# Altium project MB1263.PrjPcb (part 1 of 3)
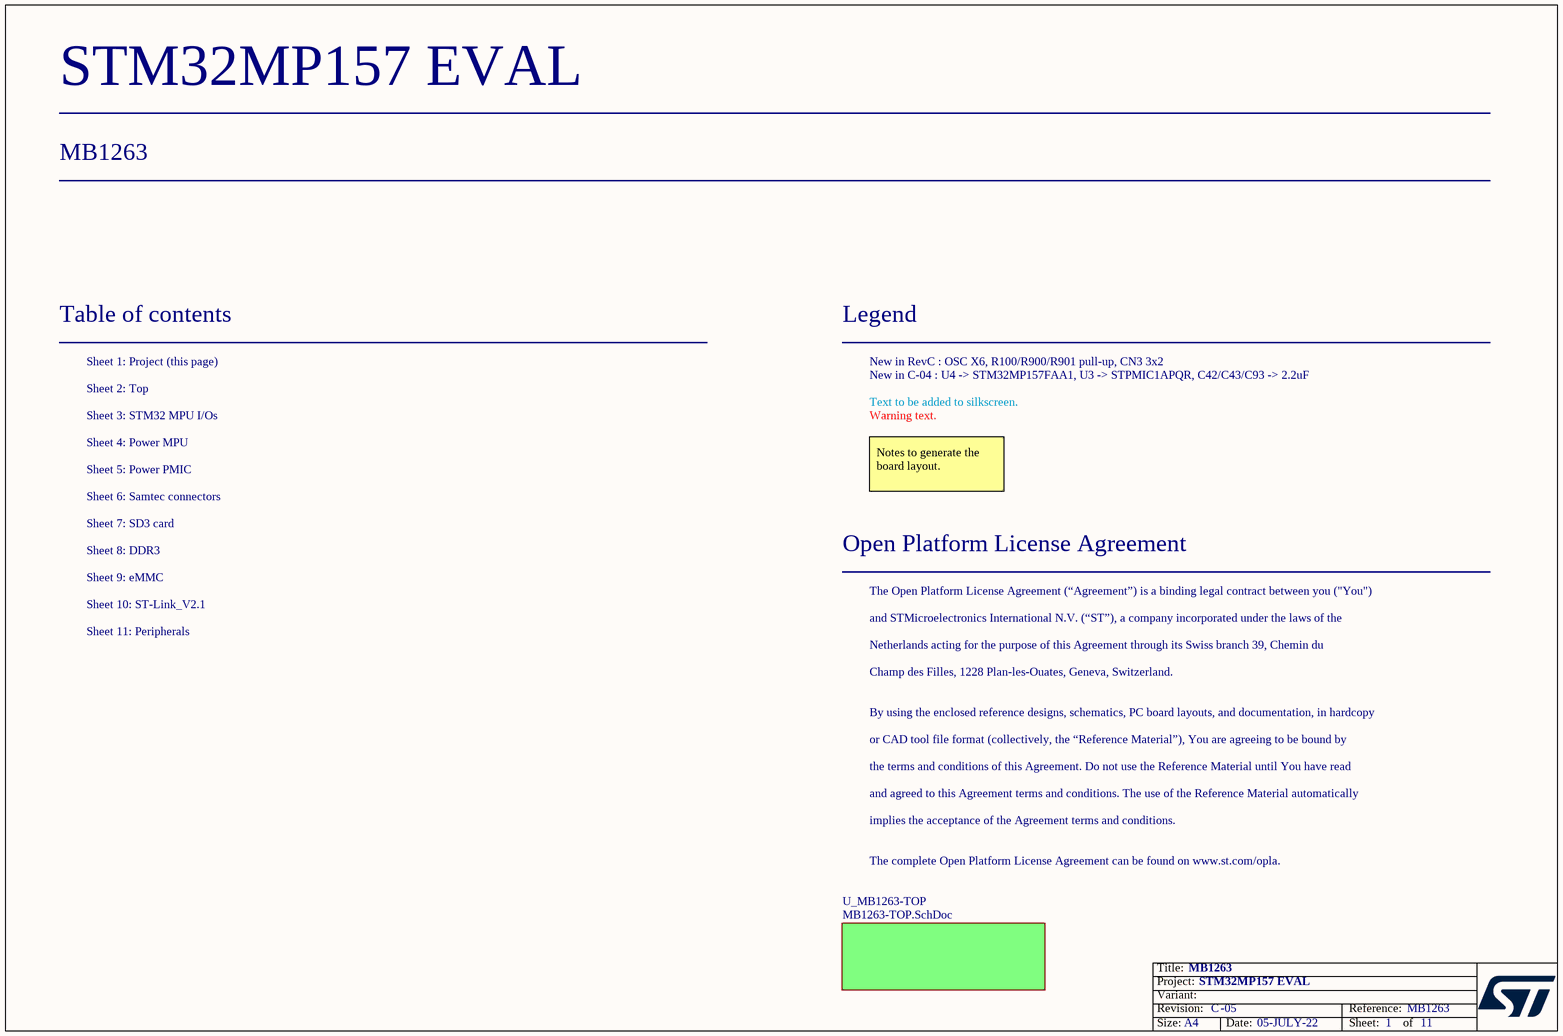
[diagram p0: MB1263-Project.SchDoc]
Board_Reference: MB1263; Board_PCB_Revision: C; Board_Name: STM32MP157 EVAL; Board_Document_Date: 05-JULY-22; Board_Assembly_Revision: 05
11 sheets, 393 parts. Net scope: flat (ports and power ports of the same name join across sheets).
Board file: MB1263.PcbDoc
Sheets:
  MB1263-Project.SchDoc
    U_MB1263-TOP = MB1263-TOP.SchDoc
      U_eMMC = eMMC.SchDoc
      U_DDR3_2x16bits = DDR3_2x16bits.SchDoc
      U_Power_PMIC = Power_PMIC.SchDoc
      U_MPU_18x18 = MPU_18x18.SchDoc
      U_SD3 card = SD3 card.SchDoc
      U_Peripherals = Peripherals.SchDoc
      U_ST_LINK_V2-1 = ST_LINK_V2-1.SCHDOC
      U_Samtec Connectors QTH_North_South = Samtec Connectors QTH_North_South.SchDoc
      U_Power_MPU = Power_MPU.SchDoc

## Sheet MB1263-Project.SchDoc: MB1263
size A4; Date: Not used; ApprovedBy: Not used; CheckedBy: Not used; Author: Not used; CompanyName: STMicroelectronics; DrawnBy: Not used; Engineer: Not used; Organization: Not used; Address1: Not used; Address2: Not used; Address3: Not used; Address4: Not used; DocumentNumber: Not used; Revision: Not used; SheetNumber: 1; SheetTotal: 11

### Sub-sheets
U_MB1263-TOP = MB1263-TOP.SchDoc: no entries

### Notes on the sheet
- Table of contents
- Sheet 1: Project (this page)
- Legend
- New in RevC : OSC X6, R100/R900/R901 pull-up, CN3 3x2
- New in C-04 : U4 -> STM32MP157FAA1, U3 -> STPMIC1APQR, C42/C43/C93 -> 2.2uF
- Sheet 2: Top
- Sheet 3: STM32 MPU I/Os
- Sheet 4: Power MPU
- Text to be added to silkscreen.
- Warning text.
- Sheet 6: Samtec connectors
- Sheet 5: Power PMIC
- Notes to generate the board layout.
- Sheet 7: SD3 card
- Sheet 9: eMMC
- Sheet 8: DDR3
- Open Platform License Agreement
- Sheet 10: ST-Link_V2.1
- Sheet 11: Peripherals
- The Open Platform License Agreement (“Agreement”) is a binding legal contract between you ("You")
- and STMicroelectronics International N.V. (“ST”), a company incorporated under the laws of the
- Netherlands acting for the purpose of this Agreement through its Swiss branch 39, Chemin du
- Champ des Filles, 1228 Plan-les-Ouates, Geneva, Switzerland.
- By using the enclosed reference designs, schematics, PC board layouts, and documentation, in hardcopy
- or CAD tool file format (collectively, the “Reference Material”), You are agreeing to be bound by
- the terms and conditions of this Agreement. Do not use the Reference Material until You have read
- and agreed to this Agreement terms and conditions. The use of the Reference Material automatically
- implies the acceptance of the Agreement terms and conditions.
- The complete Open Platform License Agreement can be found on www.st.com/opla.

## Sheet MB1263-TOP.SchDoc: MB1263-TOP
size A3; CompanyName: STMicroelectronics; DocumentNumber: MB1263; Revision: C-04; SheetNumber: 2; SheetTotal: 11; Project: STM32MP157-EVAL
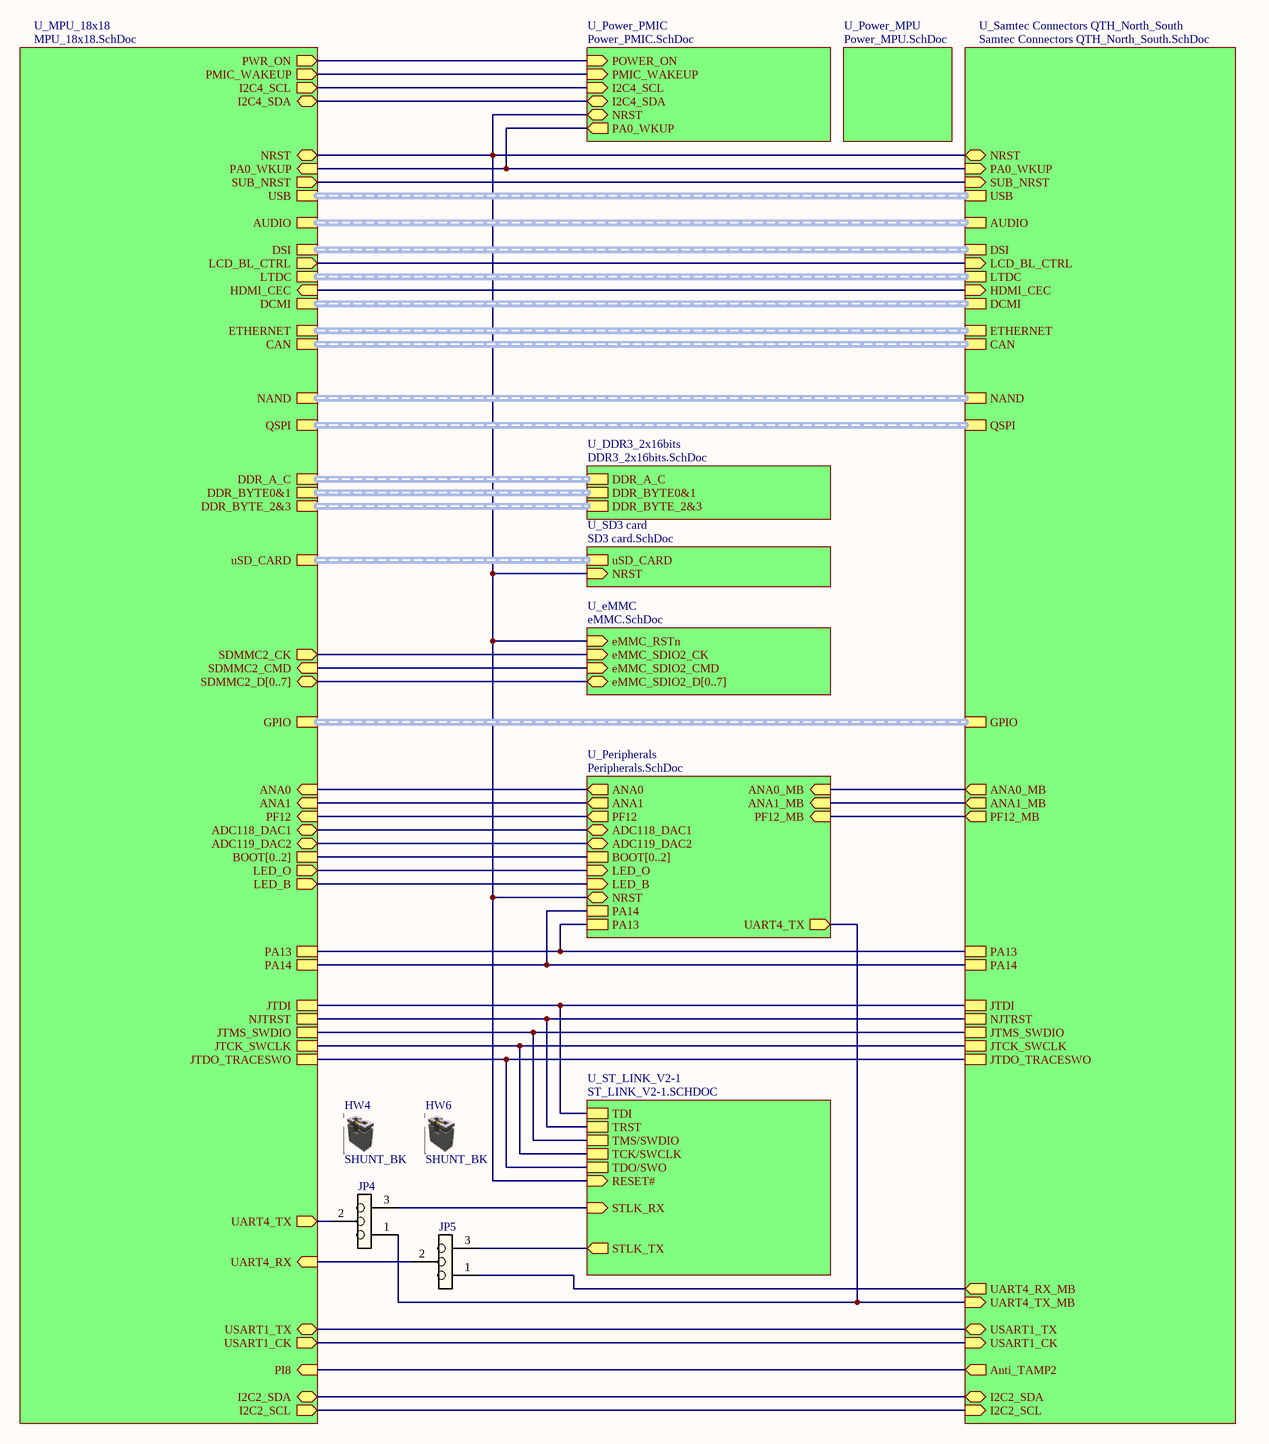
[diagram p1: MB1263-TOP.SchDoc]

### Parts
HW4  SHUNT_BK  (mechanical)
HW6  SHUNT_BK  (mechanical)
JP4  Header 3 pins  [CON_SAMTEC_TSW-103-07-F-S]  (value not drawn)
JP5  Header 3 pins  [CON_SAMTEC_TSW-103-07-F-S]  (value not drawn)

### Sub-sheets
U_DDR3_2x16bits = DDR3_2x16bits.SchDoc: DDR_A_C (harness DDR_A_C), DDR_BYTE0&1 (harness DDR_BYTE_0&1), DDR_BYTE_2&3 (harness DDR_BYTE_2&3)
U_eMMC = eMMC.SchDoc: eMMC_SDIO2_CK (in), eMMC_SDIO2_D[0..7] (bidir), eMMC_RSTn (in), eMMC_SDIO2_CMD (in)
U_MPU_18x18 = MPU_18x18.SchDoc: DDR_BYTE0&1 (harness DDR_BYTE_0&1), DDR_BYTE_2&3 (harness DDR_BYTE_2&3), DDR_A_C (harness DDR_A_C), ANA0 (in), ADC118_DAC1 (bidir), PWR_ON (out), SDMMC2_CK (out), SDMMC2_D[0..7] (bidir), SDMMC2_CMD (in), DSI (harness DSI), LCD_BL_CTRL (out), HDMI_CEC (in), USART1_TX (bidir), USART1_CK (out), CAN (harness CAN), JTMS_SWDIO, JTDI, JTDO_TRACESWO, NJTRST, JTCK_SWCLK, PA13, PA14, I2C4_SDA (bidir), I2C4_SCL (out), PA0_WKUP (in), PMIC_WAKEUP (out), NRST (bidir), UART4_TX (out), UART4_RX (in), ADC119_DAC2 (bidir), ANA1 (in), GPIO (harness GPIO), PI8 (in), USB (harness USB), NAND (harness NAND), LTDC (harness LTDC), DCMI (harness DCMI), ETHERNET (harness ETHERNET), QSPI (harness QSPI), AUDIO (harness AUDIO), uSD_CARD (harness uSD_CARD), PF12 (in), BOOT[0..2], I2C2_SDA (bidir), I2C2_SCL (out), LED_O (out), LED_B (out), SUB_NRST (out)
U_Peripherals = Peripherals.SchDoc: ADC118_DAC1 (bidir), ADC119_DAC2 (bidir), NRST (bidir), ANA0 (out), ANA1 (out), BOOT[0..2], PA13, PA14, UART4_TX (out), ANA0_MB (in), ANA1_MB (in), PF12 (out), PF12_MB (in), LED_O (in), LED_B (in)
U_Power_MPU = Power_MPU.SchDoc: no entries
U_Power_PMIC = Power_PMIC.SchDoc: I2C4_SDA (bidir), I2C4_SCL (in), PA0_WKUP (out), NRST (bidir), POWER_ON (in), PMIC_WAKEUP (in)
U_Samtec Connectors QTH_North_South = Samtec Connectors QTH_North_South.SchDoc: Anti_TAMP2 (out), USART1_TX (bidir), USART1_CK (in), GPIO (harness GPIO), LCD_BL_CTRL (in), DSI (harness DSI), JTMS_SWDIO, JTCK_SWCLK, JTDI, NJTRST, JTDO_TRACESWO, NRST (bidir), PA0_WKUP (in), CAN (harness CAN), UART4_TX_MB (in), UART4_RX_MB (out), PA13, PA14, HDMI_CEC (in), USB (harness USB), NAND (harness NAND), LTDC (harness LTDC), DCMI (harness DCMI), ETHERNET (harness ETHERNET), QSPI (harness QSPI), AUDIO (harness AUDIO), PF12_MB (out), ANA0_MB (out), ANA1_MB (out), I2C2_SCL (in), I2C2_SDA (bidir), SUB_NRST (in)
U_SD3 card = SD3 card.SchDoc: uSD_CARD (harness uSD_CARD), NRST (in)
U_ST_LINK_V2-1 = ST_LINK_V2-1.SCHDOC: STLK_RX (in), STLK_TX (out), TDI, TRST, TMS/SWDIO, TCK/SWCLK, TDO/SWO, RESET# (in)

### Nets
NetJP4_1: JP4.1 ; sheet U_Peripherals/UART4_TX, sheet U_Samtec Connectors QTH_North_South/UART4_TX_MB
NetJP4_2: JP4.2 ; sheet U_MPU_18x18/UART4_TX
NetJP4_3: JP4.3 ; sheet U_ST_LINK_V2-1/STLK_RX
NetJP5_1: JP5.1 ; sheet U_Samtec Connectors QTH_North_South/UART4_RX_MB
NetJP5_2: JP5.2 ; sheet U_MPU_18x18/UART4_RX
NetJP5_3: JP5.3 ; sheet U_ST_LINK_V2-1/STLK_TX
(unnamed): sheet U_eMMC/eMMC_SDIO2_CK, sheet U_MPU_18x18/SDMMC2_CK
(unnamed): sheet U_eMMC/eMMC_RSTn, sheet U_Power_PMIC/NRST, sheet U_MPU_18x18/NRST, sheet U_SD3 card/NRST, sheet U_Peripherals/NRST, sheet U_ST_LINK_V2-1/RESET#, sheet U_Samtec Connectors QTH_North_South/NRST  [a separate net that carries the same name]
(unnamed): sheet U_eMMC/eMMC_SDIO2_CMD, sheet U_MPU_18x18/SDMMC2_CMD  [a separate net that carries the same name]
(unnamed): sheet U_Power_PMIC/I2C4_SDA, sheet U_MPU_18x18/I2C4_SDA  [a separate net that carries the same name]
(unnamed): sheet U_Power_PMIC/I2C4_SCL, sheet U_MPU_18x18/I2C4_SCL  [a separate net that carries the same name]
(unnamed): sheet U_Power_PMIC/PA0_WKUP, sheet U_MPU_18x18/PA0_WKUP, sheet U_Samtec Connectors QTH_North_South/PA0_WKUP  [a separate net that carries the same name]
(unnamed): sheet U_Power_PMIC/POWER_ON, sheet U_MPU_18x18/PWR_ON  [a separate net that carries the same name]
(unnamed): sheet U_Power_PMIC/PMIC_WAKEUP, sheet U_MPU_18x18/PMIC_WAKEUP  [a separate net that carries the same name]
(unnamed): sheet U_MPU_18x18/ANA0, sheet U_Peripherals/ANA0  [a separate net that carries the same name]
(unnamed): sheet U_MPU_18x18/ADC118_DAC1, sheet U_Peripherals/ADC118_DAC1  [a separate net that carries the same name]
(unnamed): sheet U_MPU_18x18/LCD_BL_CTRL, sheet U_Samtec Connectors QTH_North_South/LCD_BL_CTRL  [a separate net that carries the same name]
(unnamed): sheet U_MPU_18x18/HDMI_CEC, sheet U_Samtec Connectors QTH_North_South/HDMI_CEC  [a separate net that carries the same name]
(unnamed): sheet U_MPU_18x18/USART1_TX, sheet U_Samtec Connectors QTH_North_South/USART1_TX  [a separate net that carries the same name]
(unnamed): sheet U_MPU_18x18/USART1_CK, sheet U_Samtec Connectors QTH_North_South/USART1_CK  [a separate net that carries the same name]
(unnamed): sheet U_MPU_18x18/JTMS_SWDIO, sheet U_ST_LINK_V2-1/TMS/SWDIO, sheet U_Samtec Connectors QTH_North_South/JTMS_SWDIO  [a separate net that carries the same name]
(unnamed): sheet U_MPU_18x18/JTDI, sheet U_ST_LINK_V2-1/TDI, sheet U_Samtec Connectors QTH_North_South/JTDI  [a separate net that carries the same name]
(unnamed): sheet U_MPU_18x18/JTDO_TRACESWO, sheet U_ST_LINK_V2-1/TDO/SWO, sheet U_Samtec Connectors QTH_North_South/JTDO_TRACESWO  [a separate net that carries the same name]
(unnamed): sheet U_MPU_18x18/NJTRST, sheet U_ST_LINK_V2-1/TRST, sheet U_Samtec Connectors QTH_North_South/NJTRST  [a separate net that carries the same name]
(unnamed): sheet U_MPU_18x18/JTCK_SWCLK, sheet U_ST_LINK_V2-1/TCK/SWCLK, sheet U_Samtec Connectors QTH_North_South/JTCK_SWCLK  [a separate net that carries the same name]
(unnamed): sheet U_MPU_18x18/PA13, sheet U_Peripherals/PA13, sheet U_Samtec Connectors QTH_North_South/PA13  [a separate net that carries the same name]
(unnamed): sheet U_MPU_18x18/PA14, sheet U_Peripherals/PA14, sheet U_Samtec Connectors QTH_North_South/PA14  [a separate net that carries the same name]
(unnamed): sheet U_MPU_18x18/ADC119_DAC2, sheet U_Peripherals/ADC119_DAC2  [a separate net that carries the same name]
(unnamed): sheet U_MPU_18x18/ANA1, sheet U_Peripherals/ANA1  [a separate net that carries the same name]
(unnamed): sheet U_MPU_18x18/PI8, sheet U_Samtec Connectors QTH_North_South/Anti_TAMP2  [a separate net that carries the same name]
(unnamed): sheet U_MPU_18x18/PF12, sheet U_Peripherals/PF12  [a separate net that carries the same name]
(unnamed): sheet U_MPU_18x18/I2C2_SDA, sheet U_Samtec Connectors QTH_North_South/I2C2_SDA  [a separate net that carries the same name]
(unnamed): sheet U_MPU_18x18/I2C2_SCL, sheet U_Samtec Connectors QTH_North_South/I2C2_SCL  [a separate net that carries the same name]
(unnamed): sheet U_MPU_18x18/LED_O, sheet U_Peripherals/LED_O  [a separate net that carries the same name]
(unnamed): sheet U_MPU_18x18/LED_B, sheet U_Peripherals/LED_B  [a separate net that carries the same name]
(unnamed): sheet U_MPU_18x18/SUB_NRST, sheet U_Samtec Connectors QTH_North_South/SUB_NRST  [a separate net that carries the same name]
(unnamed): sheet U_Peripherals/ANA0_MB, sheet U_Samtec Connectors QTH_North_South/ANA0_MB  [a separate net that carries the same name]
(unnamed): sheet U_Peripherals/ANA1_MB, sheet U_Samtec Connectors QTH_North_South/ANA1_MB  [a separate net that carries the same name]
(unnamed): sheet U_Peripherals/PF12_MB, sheet U_Samtec Connectors QTH_North_South/PF12_MB  [a separate net that carries the same name]

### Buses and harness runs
bus sheet U_eMMC/eMMC_SDIO2_D[0..7] = sheet U_MPU_18x18/SDMMC2_D[0..7]
bus sheet U_MPU_18x18/BOOT[0..2] = sheet U_Peripherals/BOOT[0..2]
harness sheet U_DDR3_2x16bits/DDR_A_C = sheet U_MPU_18x18/DDR_A_C
harness sheet U_DDR3_2x16bits/DDR_BYTE0&1 = sheet U_MPU_18x18/DDR_BYTE0&1
harness sheet U_DDR3_2x16bits/DDR_BYTE_2&3 = sheet U_MPU_18x18/DDR_BYTE_2&3
harness sheet U_MPU_18x18/AUDIO = sheet U_Samtec Connectors QTH_North_South/AUDIO
harness sheet U_MPU_18x18/CAN = sheet U_Samtec Connectors QTH_North_South/CAN
harness sheet U_MPU_18x18/DCMI = sheet U_Samtec Connectors QTH_North_South/DCMI
harness sheet U_MPU_18x18/DSI = sheet U_Samtec Connectors QTH_North_South/DSI
harness sheet U_MPU_18x18/ETHERNET = sheet U_Samtec Connectors QTH_North_South/ETHERNET
harness sheet U_MPU_18x18/GPIO = sheet U_Samtec Connectors QTH_North_South/GPIO
harness sheet U_MPU_18x18/LTDC = sheet U_Samtec Connectors QTH_North_South/LTDC
harness sheet U_MPU_18x18/NAND = sheet U_Samtec Connectors QTH_North_South/NAND
harness sheet U_MPU_18x18/QSPI = sheet U_Samtec Connectors QTH_North_South/QSPI
harness sheet U_MPU_18x18/USB = sheet U_Samtec Connectors QTH_North_South/USB
harness sheet U_MPU_18x18/uSD_CARD = sheet U_SD3 card/uSD_CARD

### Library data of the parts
HW4 HW6 = Shunt 2.54mm: SHUNT 2.54mm BLACK; Manuf_1: SAMTEC; Manuf_Part_1: SNT-100-BK-G; Fitted: YES; Ordered_By: Subcon
JP4 JP5 = Header 3: Header, 3-Pin; Manuf_1: Samtec; Manuf_Part_1: TSW-103-07-F-S; Fitted: YES; Ordered_By: Subcon

## Sheet eMMC.SchDoc: eMMC
size A4; CompanyName: STMicroelectronics; DocumentNumber: MB1263; Revision: C-04; SheetNumber: 9; SheetTotal: 11; Project: STM32MP157-EVAL
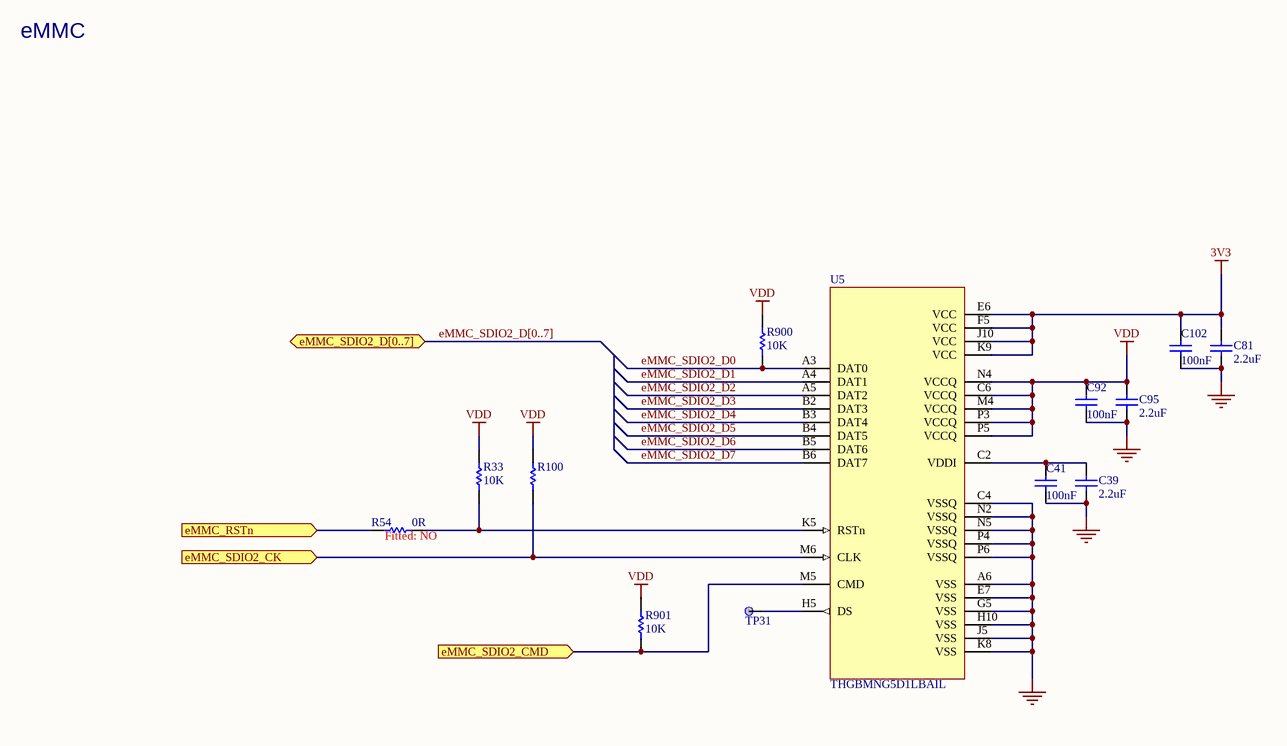
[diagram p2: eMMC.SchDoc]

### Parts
C39  2.2uF  [C0603]
C41  100nF  [C0402]
C81  2.2uF  [C0603]
C92  100nF  [C0402]
C95  2.2uF  [C0603]
C102  100nF  [C0402]
R33  10K  [R0402]
R54  0R  Fitted: NO  [R0402]
R100  10K  [R0402]  (value not drawn)
R900  10K  [R0402]
R901  10K  [R0402]
TP31  TP  [TP_SMD_1MM]  (value not drawn)  (no BOM)
U5  THGBMNG5D1LBAIL  [ICC_P-WFBGA153_13X11P5_P050]

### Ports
eMMC_RSTn (in), eMMC_SDIO2_CK (in), eMMC_SDIO2_CMD (in), eMMC_SDIO2_D[0..7] (bidir)

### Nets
3V3: C81.1 C102.2 U5.E6(VCC) U5.F5(VCC) U5.J10(VCC) U5.K9(VCC)
GND: C39.2 C41.1 C81.2 C92.1 C95.2 C102.1 U5.A6(VSS) U5.C4(VSSQ) U5.E7(VSS) U5.G5(VSS) U5.H10(VSS) U5.J5(VSS) U5.K8(VSS) U5.N2(VSSQ) U5.N5(VSSQ) U5.P4(VSSQ) U5.P6(VSSQ)
VDD: C92.2 C95.1 R33.2 R100.2 R900.2 R901.2 U5.C6(VCCQ) U5.M4(VCCQ) U5.N4(VCCQ) U5.P3(VCCQ) U5.P5(VCCQ)
eMMC_RSTn: R54.1 ; port eMMC_RSTn
eMMC_SDIO2_CK: R100.1 U5.M6(CLK) ; port eMMC_SDIO2_CK
eMMC_SDIO2_CMD: R901.1 U5.M5(CMD) ; port eMMC_SDIO2_CMD
eMMC_SDIO2_D0: R900.1 U5.A3(DAT0)
eMMC_SDIO2_D1: U5.A4(DAT1)
eMMC_SDIO2_D2: U5.A5(DAT2)
eMMC_SDIO2_D3: U5.B2(DAT3)
eMMC_SDIO2_D4: U5.B3(DAT4)
eMMC_SDIO2_D5: U5.B4(DAT5)
eMMC_SDIO2_D6: U5.B5(DAT6)
eMMC_SDIO2_D7: U5.B6(DAT7)
NetC39_1: C39.1 C41.2 U5.C2(VDDI)
NetR33_1: R33.1 R54.2 U5.K5(RSTn)
NetTP31_1: TP31.1 U5.H5(DS)

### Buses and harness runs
bus eMMC_SDIO2_D[0..7] = port eMMC_SDIO2_D[0..7]

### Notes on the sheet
- eMMC

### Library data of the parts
C39 C81 C95 = Cap_2.2uF_X5R_10%_0603: Capacitor,2.2uF,10V, X5R,10%,0603,YAGEO; Manuf_Part_1: CC0603KRX5R6BB225; Manuf_Part_2: C0603C225K8PACTU; Manuf_2: KEMET; Fitted: YES; Ordered_By: Subcon
C41 C92 C102 = Cap_100nF_X7R_10%_0402: Capacitor,100nF,16V,X7R,10%,0402,YAGEO; Manuf_Part_1: CC0402KRX7R7BB104; Fitted: YES; Ordered_By: Subcon
R33 R100 R900 R901 = Res_10K_1%_0402: Resistor,10K,0402,1%,YAGEO; Manuf_Part_1: RC0402FR-0710KL; Order_Code: 9239359RL; Fitted: YES; Ordered_By: Subcon
R54 = Res_0_5%_0402: Resistor,0R,0402,5%,YAGEO; Manuf_Part_1: RC0402JR-070RL; Order_Code: 2363467; Ordered_By: Subcon
TP31 = TP 1mm: Test Point; Fitted: YES
U5 = eMMC_THGBMNG5D1LBAIL: eMMC 4GB 153 Balls WFBGA 15nm; Manuf_1: KIOXIA; Manuf_Part_1: THGBMTG5D1LBAIL; ECCN_US/EU: EAR99; Fitted: YES; Ordered_By: Subcon

## Sheet DDR3_2x16bits.SchDoc: 2X DDR3L 16 bits
size A4; Date: 30-MAR-2016; Author: F.L; CompanyName: STMicroelectronics; Organization: MCD/TOOLS/LMS; Address1: 12, Rue Jules HOROWITZ; Address2: 38019 Grenoble; Address3: FRANCE; DocumentNumber: MB1263; Revision: C-04; SheetNumber: 8; SheetTotal: 11; Project: STM32MP157-EVAL; PageSetup: Record=PageOptions¦CenterHorizontal=True¦CenterVertical=True¦PrintScale=1.39¦XCorrection=1.00¦YCorrection=1.00¦PrintKind=1¦BorderSize=5000000¦LeftOffset=0¦BottomOffset=0¦Orientation=2¦PaperLength=1000¦PaperWidth=1000¦Scale=100¦PaperSource=15¦PrintQuality=600¦MediaType=1¦DitherType=10¦PrintScaleMode=1¦PaperKind=A3¦PaperIndex=8
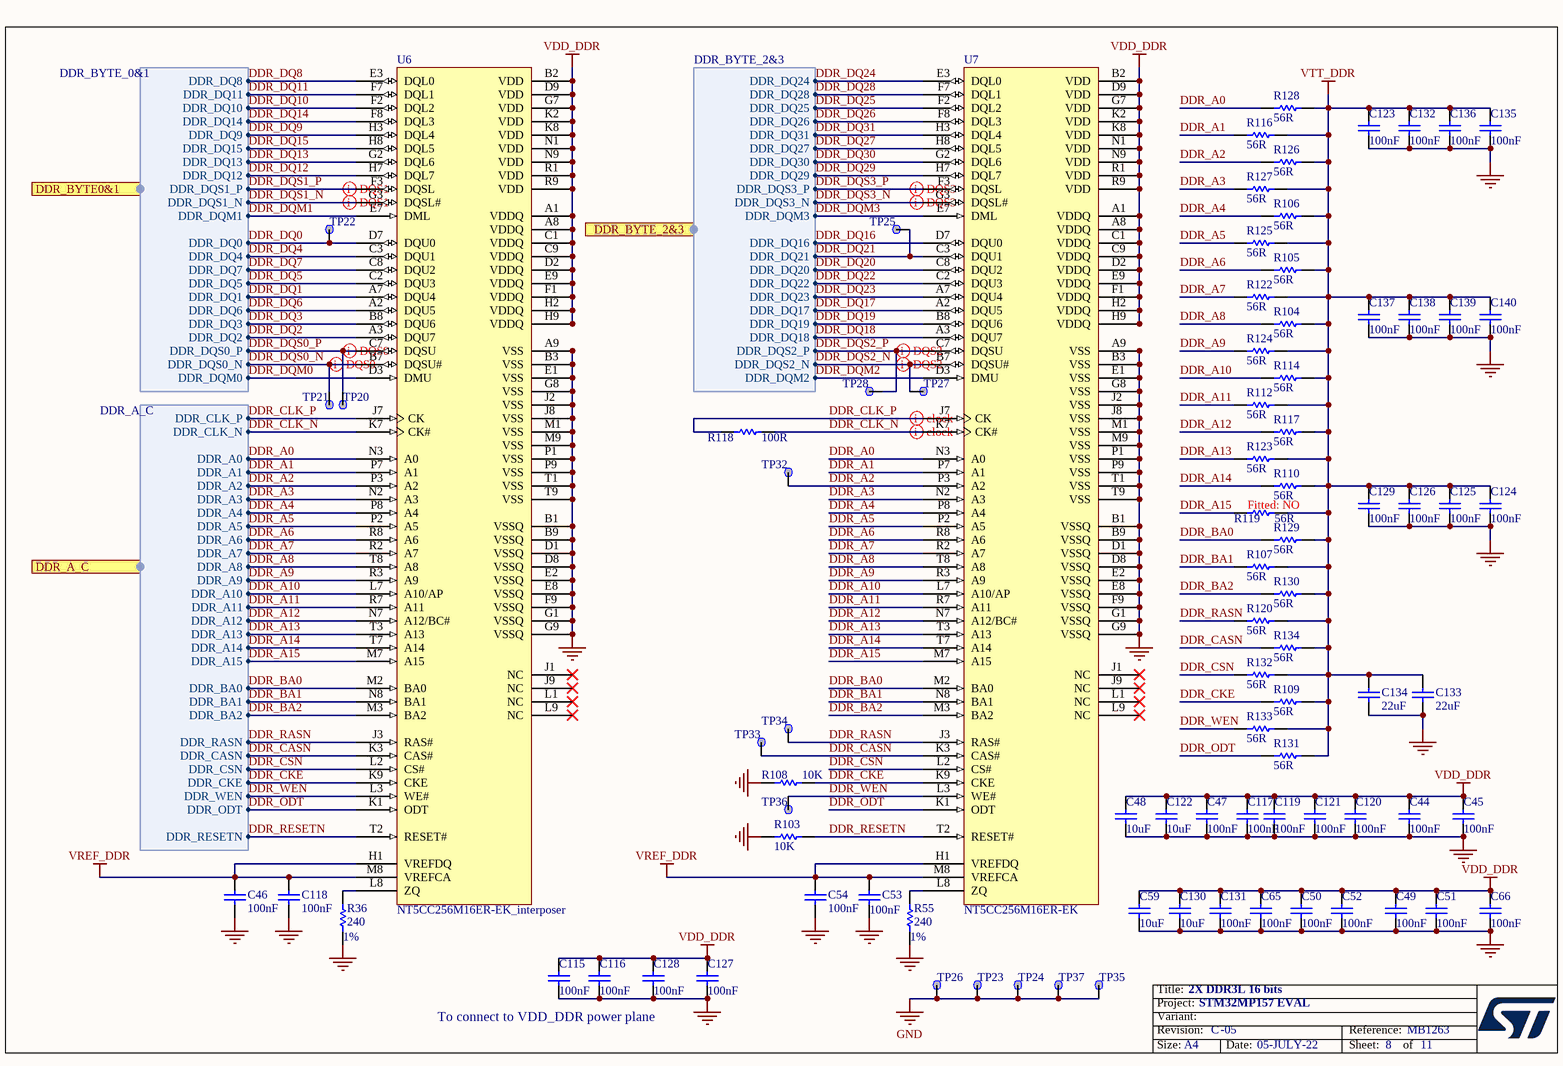
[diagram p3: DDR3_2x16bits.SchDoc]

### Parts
C44  100nF  [C0402]
C45  100nF  [C0402]
C46  100nF  [C0402]
C47  100nF  [C0402]
C48  10uF  [C0603]
C49  100nF  [C0402]
C50  100nF  [C0402]
C51  100nF  [C0402]
C52  100nF  [C0402]
C53  100nF  [C0402]
C54  100nF  [C0402]
C59  10uF  [C0603]
C65  100nF  [C0402]
C66  100nF  [C0402]
C115  100nF  [C0402]
C116  100nF  [C0402]
C117  100nF  [C0402]
C118  100nF  [C0402]
C119  100nF  [C0402]
C120  100nF  [C0402]
C121  100nF  [C0402]
C122  10uF  [C0603]
C123  100nF  [C0402]
C124  100nF  [C0402]
C125  100nF  [C0402]
C126  100nF  [C0402]
C127  100nF  [C0402]
C128  100nF  [C0402]
C129  100nF  [C0402]
C130  10uF  [C0603]
C131  100nF  [C0402]
C132  100nF  [C0402]
C133  22uF  [C0603]
C134  22uF  [C0603]
C135  100nF  [C0402]
C136  100nF  [C0402]
C137  100nF  [C0402]
C138  100nF  [C0402]
C139  100nF  [C0402]
C140  100nF  [C0402]
R36  240  Precision: 1%  [R0402]
R55  240  Precision: 1%  [R0402]
R103  10K  [R0402]
R104  56R  [R0402]
R105  56R  [R0402]
R106  56R  [R0402]
R107  56R  [R0402]
R108  10K  [R0402]
R109  56R  [R0402]
R110  56R  [R0402]
R112  56R  [R0402]
R114  56R  [R0402]
R116  56R  [R0402]
R117  56R  [R0402]
R118  100R  [R0402]
R119  56R  Fitted: NO  [R0402]
R120  56R  [R0402]
R122  56R  [R0402]
R123  56R  [R0402]
R124  56R  [R0402]
R125  56R  [R0402]
R126  56R  [R0402]
R127  56R  [R0402]
R128  56R  [R0402]
R129  56R  [R0402]
R130  56R  [R0402]
R131  56R  [R0402]
R132  56R  [R0402]
R133  56R  [R0402]
R134  56R  [R0402]
TP20  TP 0.3  [TP_SMD_0-3MM]  (value not drawn)  (no BOM)
TP21  TP 0.3  [TP_SMD_0-3MM]  (value not drawn)  (no BOM)
TP22  TP 0.6  [TP_SMD_0-6MM]  (value not drawn)  (no BOM)
TP23  TP 0.6  [TP_SMD_0-6MM]  (value not drawn)  (no BOM)
TP24  TP 0.6  [TP_SMD_0-6MM]  (value not drawn)  (no BOM)
TP25  TP 0.6  [TP_SMD_0-6MM]  (value not drawn)  (no BOM)
TP26  TP 0.6  [TP_SMD_0-6MM]  (value not drawn)  (no BOM)
TP27  TP 0.3  [TP_SMD_0-3MM]  (value not drawn)  (no BOM)
TP28  TP 0.3  [TP_SMD_0-3MM]  (value not drawn)  (no BOM)
TP32  TP 0.6  [TP_SMD_0-6MM]  (value not drawn)  (no BOM)
TP33  TP 0.6  [TP_SMD_0-6MM]  (value not drawn)  (no BOM)
TP34  TP 0.6  [TP_SMD_0-6MM]  (value not drawn)  (no BOM)
TP35  TP 0.6  [TP_SMD_0-6MM]  (value not drawn)  (no BOM)
TP36  TP 0.6  [TP_SMD_0-6MM]  (value not drawn)  (no BOM)
TP37  TP 0.6  [TP_SMD_0-6MM]  (value not drawn)  (no BOM)
U6  NT5CC256M16ER-EK_interposer  [ICC_FBGA96_9X13_8X14_P080_DI _INTERPOSER]
U7  NT5CC256M16ER-EK  [ICC_FBGA96_9X13_8X14_P080_DI]

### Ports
DDR_A_C (harness DDR_A_C), DDR_BYTE0&1 (harness DDR_BYTE_0&1), DDR_BYTE_2&3 (harness DDR_BYTE_2&3)

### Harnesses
DDR_A_C: DDR_A4, DDR_A0, DDR_A2, DDR_A1, DDR_A6, DDR_A3, DDR_A5, DDR_A7, DDR_A8, DDR_A9, DDR_A14, DDR_A10, DDR_A12, DDR_A11, DDR_BA0, DDR_A13, DDR_A15, DDR_BA1, DDR_BA2, DDR_RASN, DDR_CASN, DDR_CSN, DDR_CKE, DDR_WEN, DDR_ODT, DDR_CLK_P, DDR_CLK_N, DDR_RESETN
DDR_BYTE_0&1: DDR_DQ9, DDR_DQ8, DDR_DQ10, DDR_DQ11, DDR_DQ13, DDR_DQ14, DDR_DQ15, DDR_DQ12, DDR_DQS1_P, DDR_DQS1_N, DDR_DQ7, DDR_DQM1, DDR_DQ0, DDR_DQ1, DDR_DQ4, DDR_DQ5, DDR_DQ6, DDR_DQ3, DDR_DQ2, DDR_DQS0_P, DDR_DQS0_N, DDR_DQM0
DDR_BYTE_2&3: DDR_DQ24, DDR_DQ28, DDR_DQ25, DDR_DQ26, DDR_DQ31, DDR_DQ27, DDR_DQ30, DDR_DQ29, DDR_DQS3_P, DDR_DQS3_N, DDR_DQM3, DDR_DQ16, DDR_DQ21, DDR_DQ20, DDR_DQ22, DDR_DQ23, DDR_DQ17, DDR_DQ19, DDR_DQ18, DDR_DQS2_P, DDR_DQS2_N, DDR_DQM2

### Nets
GND: C44.2 C45.2 C46.2 C47.2 C48.1 C49.2 C50.2 C51.2 C52.2 C53.2 C54.2 C59.1 C65.2 C66.2 C115.2 C116.2 C117.2 C118.2 C119.2 C120.2 C121.2 C122.1 C123.2 C124.2 C125.2 C126.2 C127.2 C128.2 C129.2 C130.1 C131.2 C132.2 C133.1 C134.1 C135.2 C136.2 C137.2 C138.2 C139.2 C140.2 R36.1 R55.1 R103.1 R108.1 TP23.1 TP24.1 TP26.1 TP35.1 TP37.1 U6.A9(VSS) U6.B1(VSSQ) U6.B3(VSS) U6.B9(VSSQ) U6.D1(VSSQ) U6.D8(VSSQ) U6.E1(VSS) U6.E2(VSSQ) U6.E8(VSSQ) U6.F9(VSSQ) U6.G1(VSSQ) U6.G8(VSS) U6.G9(VSSQ) U6.J2(VSS) U6.J8(VSS) U6.M1(VSS) U6.M9(VSS) U6.P1(VSS) U6.P9(VSS) U6.T1(VSS) U6.T9(VSS) U7.A9(VSS) U7.B1(VSSQ) U7.B3(VSS) U7.B9(VSSQ) U7.D1(VSSQ) U7.D8(VSSQ) U7.E1(VSS) U7.E2(VSSQ) U7.E8(VSSQ) U7.F9(VSSQ) U7.G1(VSSQ) U7.G8(VSS) U7.G9(VSSQ) U7.J2(VSS) U7.J8(VSS) U7.M1(VSS) U7.M9(VSS) U7.P1(VSS) U7.P9(VSS) U7.T1(VSS) U7.T9(VSS)
VDD_DDR: C44.1 C45.1 C47.1 C48.2 C49.1 C50.1 C51.1 C52.1 C59.2 C65.1 C66.1 C115.1 C116.1 C117.1 C119.1 C120.1 C121.1 C122.2 C127.1 C128.1 C130.2 C131.1 U6.A1(VDDQ) U6.A8(VDDQ) U6.B2(VDD) U6.C1(VDDQ) U6.C9(VDDQ) U6.D2(VDDQ) U6.D9(VDD) U6.E9(VDDQ) U6.F1(VDDQ) U6.G7(VDD) U6.H2(VDDQ) U6.H9(VDDQ) U6.K2(VDD) U6.K8(VDD) U6.N1(VDD) U6.N9(VDD) U6.R1(VDD) U6.R9(VDD) U7.A1(VDDQ) U7.A8(VDDQ) U7.B2(VDD) U7.C1(VDDQ) U7.C9(VDDQ) U7.D2(VDDQ) U7.D9(VDD) U7.E9(VDDQ) U7.F1(VDDQ) U7.G7(VDD) U7.H2(VDDQ) U7.H9(VDDQ) U7.K2(VDD) U7.K8(VDD) U7.N1(VDD) U7.N9(VDD) U7.R1(VDD) U7.R9(VDD)
VREF_DDR: C46.1 C53.1 C54.1 C118.1 U6.H1(VREFDQ) U6.M8(VREFCA) U7.H1(VREFDQ) U7.M8(VREFCA)
VTT_DDR: C123.1 C124.1 C125.1 C126.1 C129.1 C132.1 C133.2 C134.2 C135.1 C136.1 C137.1 C138.1 C139.1 C140.1 R104.2 R105.2 R106.2 R107.2 R109.2 R110.2 R112.2 R114.2 R116.2 R117.2 R119.2 R120.2 R122.2 R123.2 R124.2 R125.2 R126.2 R127.2 R128.2 R129.2 R130.2 R131.2 R132.2 R133.2 R134.2
DDR_A0: R128.1 U6.N3(A0) U7.N3(A0) ; port DDR_A_C.DDR_A0
DDR_A1: R116.1 U6.P7(A1) U7.P7(A1) ; port DDR_A_C.DDR_A1
DDR_A2: R126.1 TP32.1 U6.P3(A2) U7.P3(A2) ; port DDR_A_C.DDR_A2
DDR_A3: R127.1 U6.N2(A3) U7.N2(A3) ; port DDR_A_C.DDR_A3
DDR_A4: R106.1 U6.P8(A4) U7.P8(A4) ; port DDR_A_C.DDR_A4
DDR_A5: R125.1 U6.P2(A5) U7.P2(A5) ; port DDR_A_C.DDR_A5
DDR_A6: R105.1 U6.R8(A6) U7.R8(A6) ; port DDR_A_C.DDR_A6
DDR_A7: R122.1 U6.R2(A7) U7.R2(A7) ; port DDR_A_C.DDR_A7
DDR_A8: R104.1 U6.T8(A8) U7.T8(A8) ; port DDR_A_C.DDR_A8
DDR_A9: R124.1 U6.R3(A9) U7.R3(A9) ; port DDR_A_C.DDR_A9
DDR_A10: R114.1 U6.L7(A10/AP) U7.L7(A10/AP) ; port DDR_A_C.DDR_A10
DDR_A11: R112.1 U6.R7(A11) U7.R7(A11) ; port DDR_A_C.DDR_A11
DDR_A12: R117.1 U6.N7(A12/BC#) U7.N7(A12/BC#) ; port DDR_A_C.DDR_A12
DDR_A13: R123.1 U6.T3(A13) U7.T3(A13) ; port DDR_A_C.DDR_A13
DDR_A14: R110.1 U6.T7(A14) U7.T7(A14) ; port DDR_A_C.DDR_A14
DDR_A15: R119.1 U6.M7(A15) U7.M7(A15) ; port DDR_A_C.DDR_A15
DDR_BA0: R129.1 U6.M2(BA0) U7.M2(BA0) ; port DDR_A_C.DDR_BA0
DDR_BA1: R107.1 U6.N8(BA1) U7.N8(BA1) ; port DDR_A_C.DDR_BA1
DDR_BA2: R130.1 U6.M3(BA2) U7.M3(BA2) ; port DDR_A_C.DDR_BA2
DDR_CASN: R134.1 TP33.1 U6.K3(CAS#) U7.K3(CAS#) ; port DDR_A_C.DDR_CASN
DDR_CKE: R108.2 R109.1 U6.K9(CKE) U7.K9(CKE) ; port DDR_A_C.DDR_CKE
DDR_CLK_N: R118.2 U6.K7(CK#) U7.K7(CK#) ; port DDR_A_C.DDR_CLK_N
DDR_CLK_P: R118.1 U6.J7(CK) U7.J7(CK) ; port DDR_A_C.DDR_CLK_P
DDR_CSN: R132.1 U6.L2(CS#) U7.L2(CS#) ; port DDR_A_C.DDR_CSN
DDR_DQ0: TP22.1 U6.D7(DQU0) ; port DDR_BYTE0&1.DDR_DQ0
DDR_DQ1: U6.A7(DQU4) ; port DDR_BYTE0&1.DDR_DQ1
DDR_DQ2: U6.A3(DQU7) ; port DDR_BYTE0&1.DDR_DQ2
DDR_DQ3: U6.B8(DQU6) ; port DDR_BYTE0&1.DDR_DQ3
DDR_DQ4: U6.C3(DQU1) ; port DDR_BYTE0&1.DDR_DQ4
DDR_DQ5: U6.C2(DQU3) ; port DDR_BYTE0&1.DDR_DQ5
DDR_DQ6: U6.A2(DQU5) ; port DDR_BYTE0&1.DDR_DQ6
DDR_DQ7: U6.C8(DQU2) ; port DDR_BYTE0&1.DDR_DQ7
DDR_DQ8: U6.E3(DQL0) ; port DDR_BYTE0&1.DDR_DQ8
DDR_DQ9: U6.H3(DQL4) ; port DDR_BYTE0&1.DDR_DQ9
DDR_DQ10: U6.F2(DQL2) ; port DDR_BYTE0&1.DDR_DQ10
DDR_DQ11: U6.F7(DQL1) ; port DDR_BYTE0&1.DDR_DQ11
DDR_DQ12: U6.H7(DQL7) ; port DDR_BYTE0&1.DDR_DQ12
DDR_DQ13: U6.G2(DQL6) ; port DDR_BYTE0&1.DDR_DQ13
DDR_DQ14: U6.F8(DQL3) ; port DDR_BYTE0&1.DDR_DQ14
DDR_DQ15: U6.H8(DQL5) ; port DDR_BYTE0&1.DDR_DQ15
DDR_DQ16: U7.D7(DQU0) ; port DDR_BYTE_2&3.DDR_DQ16
DDR_DQ17: U7.A2(DQU5) ; port DDR_BYTE_2&3.DDR_DQ17
DDR_DQ18: U7.A3(DQU7) ; port DDR_BYTE_2&3.DDR_DQ18
DDR_DQ19: U7.B8(DQU6) ; port DDR_BYTE_2&3.DDR_DQ19
DDR_DQ20: U7.C8(DQU2) ; port DDR_BYTE_2&3.DDR_DQ20
DDR_DQ21: TP25.1 U7.C3(DQU1) ; port DDR_BYTE_2&3.DDR_DQ21
DDR_DQ22: U7.C2(DQU3) ; port DDR_BYTE_2&3.DDR_DQ22
DDR_DQ23: U7.A7(DQU4) ; port DDR_BYTE_2&3.DDR_DQ23
DDR_DQ24: U7.E3(DQL0) ; port DDR_BYTE_2&3.DDR_DQ24
DDR_DQ25: U7.F2(DQL2) ; port DDR_BYTE_2&3.DDR_DQ25
DDR_DQ26: U7.F8(DQL3) ; port DDR_BYTE_2&3.DDR_DQ26
DDR_DQ27: U7.H8(DQL5) ; port DDR_BYTE_2&3.DDR_DQ27
DDR_DQ28: U7.F7(DQL1) ; port DDR_BYTE_2&3.DDR_DQ28
DDR_DQ29: U7.H7(DQL7) ; port DDR_BYTE_2&3.DDR_DQ29
DDR_DQ30: U7.G2(DQL6) ; port DDR_BYTE_2&3.DDR_DQ30
DDR_DQ31: U7.H3(DQL4) ; port DDR_BYTE_2&3.DDR_DQ31
DDR_DQM0: U6.D3(DMU) ; port DDR_BYTE0&1.DDR_DQM0
DDR_DQM1: U6.E7(DML) ; port DDR_BYTE0&1.DDR_DQM1
DDR_DQM2: U7.D3(DMU) ; port DDR_BYTE_2&3.DDR_DQM2
DDR_DQM3: U7.E7(DML) ; port DDR_BYTE_2&3.DDR_DQM3
DDR_DQS0_N: TP21.1 U6.B7(DQSU#) ; port DDR_BYTE0&1.DDR_DQS0_N
DDR_DQS0_P: TP20.1 U6.C7(DQSU) ; port DDR_BYTE0&1.DDR_DQS0_P
DDR_DQS1_N: U6.G3(DQSL#) ; port DDR_BYTE0&1.DDR_DQS1_N
DDR_DQS1_P: U6.F3(DQSL) ; port DDR_BYTE0&1.DDR_DQS1_P
DDR_DQS2_N: TP27.1 U7.B7(DQSU#) ; port DDR_BYTE_2&3.DDR_DQS2_N
DDR_DQS2_P: TP28.1 U7.C7(DQSU) ; port DDR_BYTE_2&3.DDR_DQS2_P
DDR_DQS3_N: U7.G3(DQSL#) ; port DDR_BYTE_2&3.DDR_DQS3_N
DDR_DQS3_P: U7.F3(DQSL) ; port DDR_BYTE_2&3.DDR_DQS3_P
DDR_ODT: R131.1 U6.K1(ODT) U7.K1(ODT) ; port DDR_A_C.DDR_ODT
DDR_RASN: R120.1 TP34.1 U6.J3(RAS#) U7.J3(RAS#) ; port DDR_A_C.DDR_RASN
DDR_RESETN: R103.2 U6.T2(RESET#) U7.T2(RESET#) ; port DDR_A_C.DDR_RESETN
DDR_WEN: R133.1 TP36.1 U6.L3(WE#) U7.L3(WE#) ; port DDR_A_C.DDR_WEN
NetR36_2: R36.2 U6.L8(ZQ)
NetR55_2: R55.2 U7.L8(ZQ)

Not connected (* = marked no-connect by the designer): U6 J1(NC)* J9(NC)* L1(NC)* L9(NC)*; U7 J1(NC)* J9(NC)* L1(NC)* L9(NC)*

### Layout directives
differential pair: DDR_CLK_N, DDR_CLK_P, DDR_DQS0_N, DDR_DQS0_P, DDR_DQS1_N, DDR_DQS1_P, DDR_DQS2_N, DDR_DQS2_P, DDR_DQS3_N, DDR_DQS3_P

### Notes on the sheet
- To connect to VDD_DDR power plane

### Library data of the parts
C44-C47 C49-C54 C65 C66 C115-C121 C123-C129 C131 C132 C135-C140 = Cap_100nF_X7R_10%_0402: as C41 on sheet eMMC
C48 C59 C122 C130 = Cap_10uF_X5R_10%_0603: Capacitor,10uF,6.3V,X5R,10%,0603,YAGEO; Manuf_Part_1: CC0603KRX5R5BB106; Ordered_By: Subcon; Fitted: YES
C133 C134 = Cap_22uF_X5R_20%_0603_MURATA: Capacitor MLCC 22µF 20% 6,3V 7,5µF@3,3V ESR=4mohm@100kHz  Z=5mohm@2MHz X5R 0603; Manuf_Part_1: GRM188R60J226MEA0J; Manuf_1: MURATA; Fitted: YES; Ordered_By: Subcon
R36 R55 = Res_240_1%_0402: Resistor,240R,0402,1%,YAGEO; Manuf_Part_1: RC0402FR-07240RL; Fitted: YES; Ordered_By: Subcon
R103 R108 = Res_10K_1%_0402: as R33 on sheet eMMC
R104-R107 R109 R110 R112 R114 R116 R117 R120 R122-R134 = Res_56_1%_0402: Resistor,56R,0402,1%,YAGEO; Manuf_Part_1: RC0402FR-0756RL; Order_Code: 9239081RL; Fitted: YES; Ordered_By: Subcon
R118 = Res_100_1%_0402: Resistor,100R,0402,1%,YAGEO; Manuf_Part_1: RC0402FR-07100RL; Order_Code: 9239111; Fitted: YES; Ordered_By: Subcon
R119 = Res_56_1%_0402: Resistor,56R,0402,1%,YAGEO; Manuf_Part_1: RC0402FR-0756RL; Order_Code: 9239081RL; Ordered_By: Subcon
TP20 TP21 TP27 TP28 = TP 0.3mm: Test Point; Fitted: YES
TP22-TP26 TP32-TP37 = TP 0.6mm: Test Point; Fitted: YES
U6 = NT5CC256M16ER-EK_interposer: DDR3L, 16 bits, 4Gb, NANYA, 20nm; ECCN_US/EU: EAR99; Fitted: YES; Ordered_By: Subcon
U7 = NT5CC256M16ER-EK: DDR3L, 16 bits, 4Gb, NANYA, 20nm; ECCN_US/EU: EAR99; Fitted: YES; Ordered_By: Subcon

## Sheet Power_PMIC.SchDoc: PMIC
size A3; Date: 01-DEC-2013; CompanyName: STMicroelectronics; Organization: Microcontrollers Division; Address1: 12, Rue Jules HOROWITZ; Address2: 38019 Grenoble; Address3: FRANCE; DocumentNumber: MB1263; Revision: C-04; SheetNumber: 5; SheetTotal: 11; Project: STM32MP157-EVAL
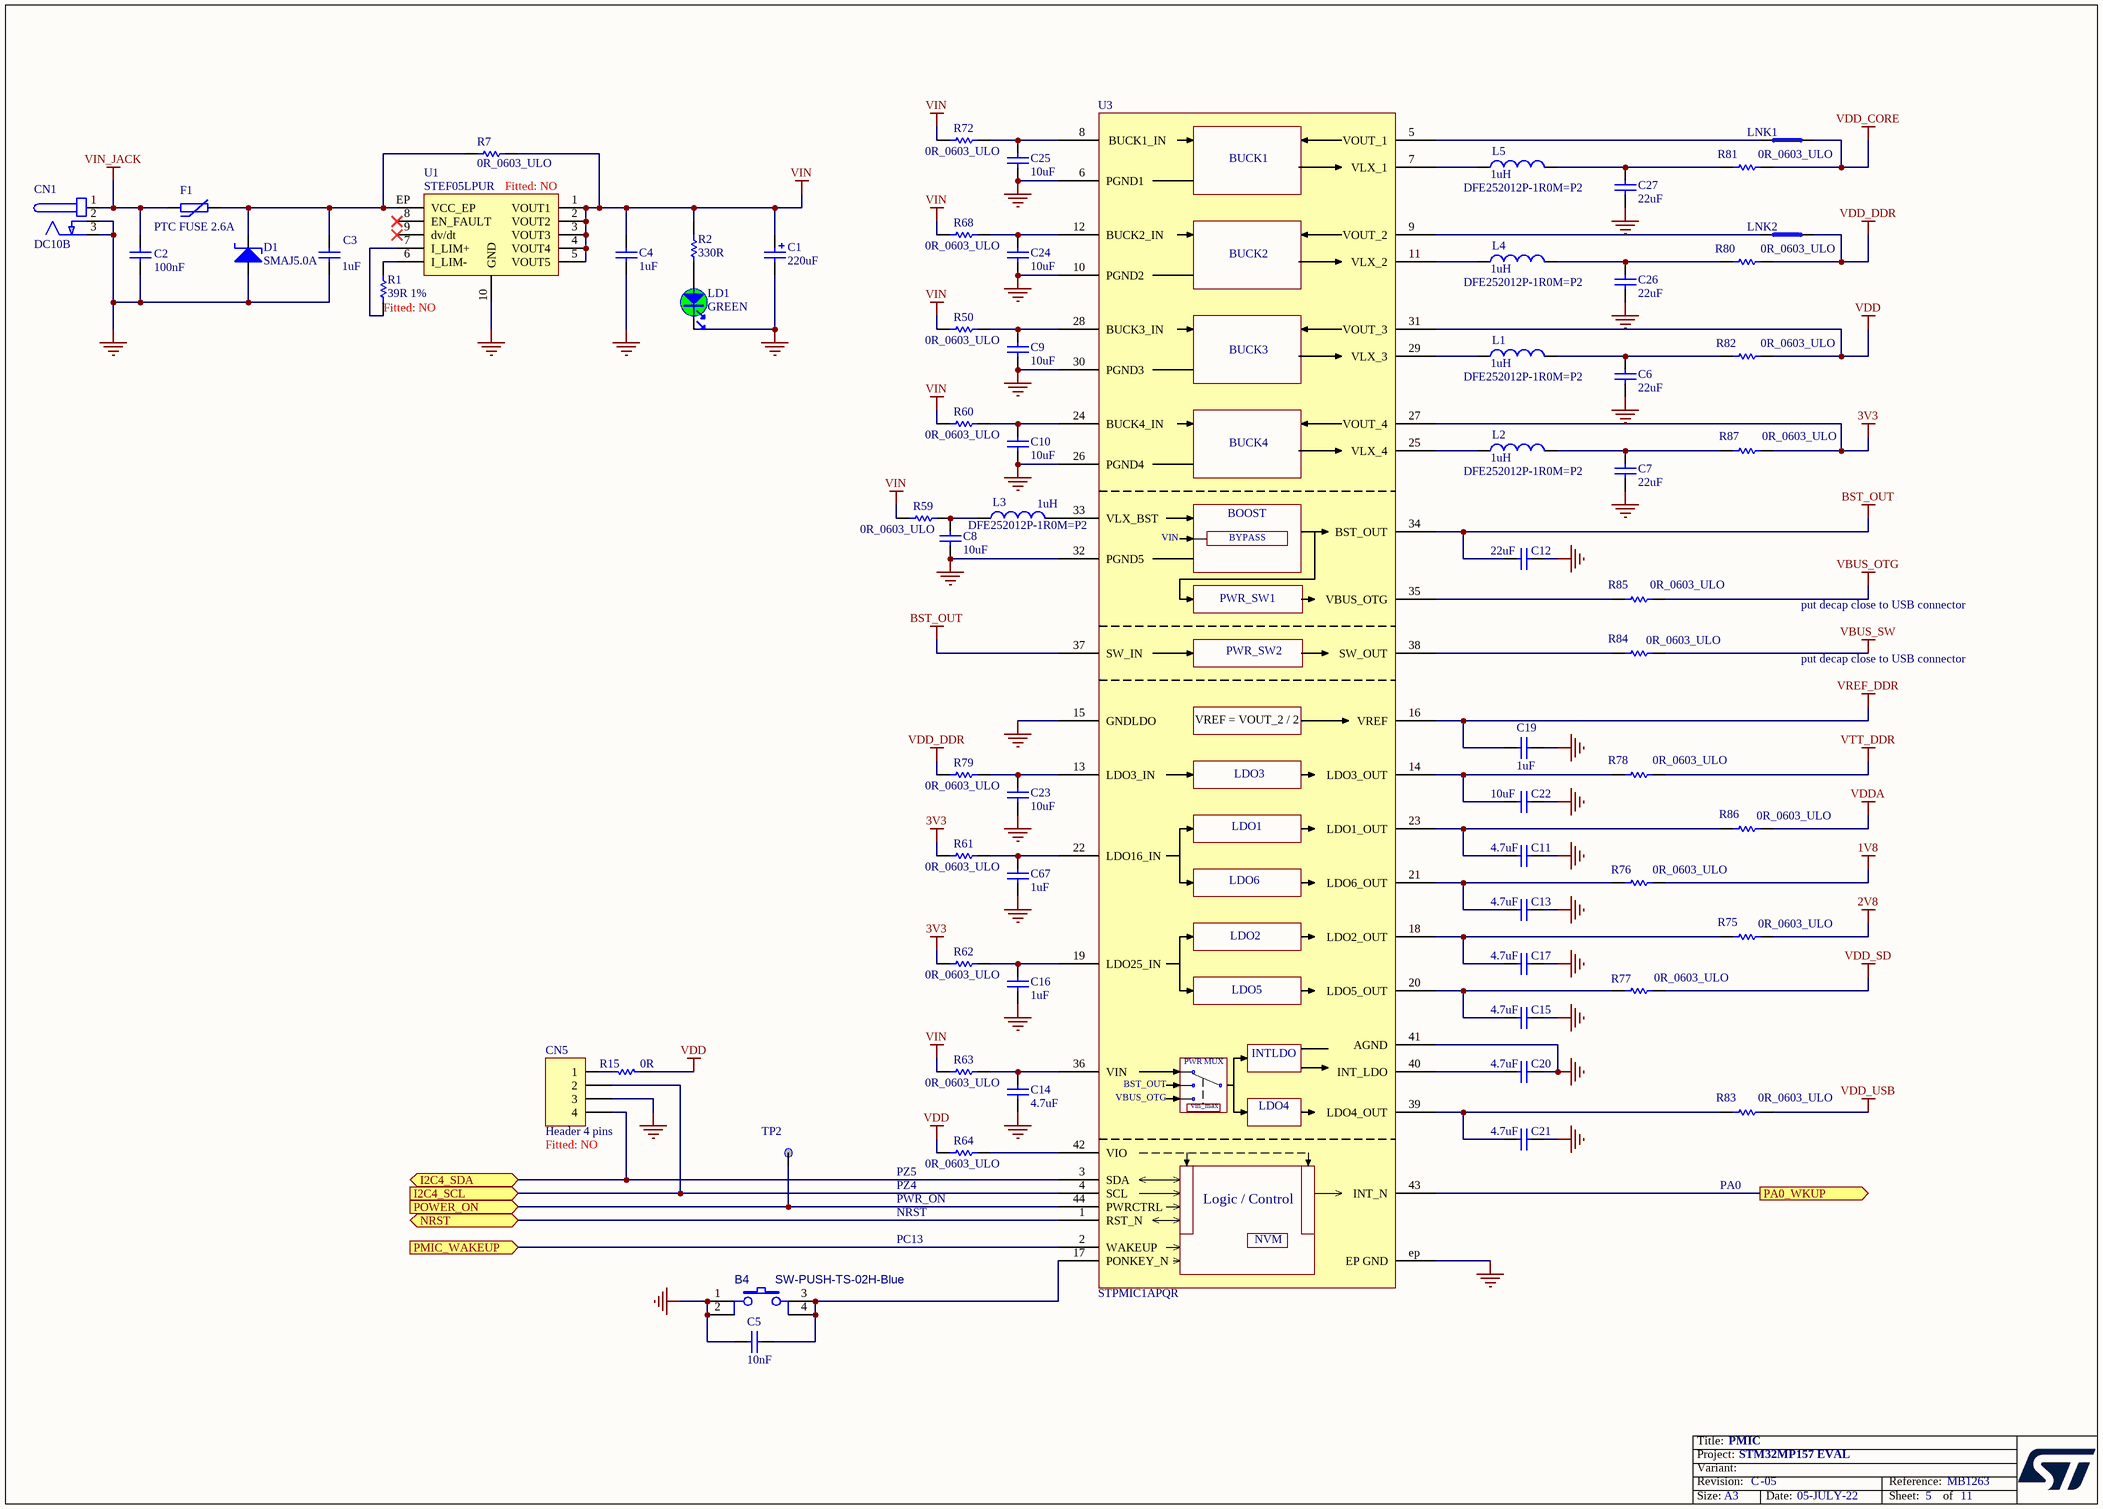
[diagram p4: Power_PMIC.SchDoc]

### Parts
B4  SW-PUSH-TS-02H-Blue  [SWI_JIUBABA_C-TS-02H-2-5-B-V-T_R_BLUE]
C1  220uF  [CPOL_TAJ-C_2312_H2P6]
C2  100nF  [C0402]
C3  1uF  [C0603]
C4  1uF  [C0603]
C5  10nF  [C0402]
C6  22uF  [C0603]
C7  22uF  [C0603]
C8  10uF  [C0603]
C9  10uF  [C0603]
C10  10uF  [C0603]
C11  4.7uF  [C0402]
C12  22uF  [C0603]
C13  4.7uF  [C0402]
C14  4.7uF  [C0402]
C15  4.7uF  [C0402]
C16  1uF  [C0402]
C17  4.7uF  [C0402]
C19  1uF  [C0402]
C20  4.7uF  [C0402]
C21  4.7uF  [C0402]
C22  10uF  [C0603]
C23  10uF  [C0603]
C24  10uF  [C0603]
C25  10uF  [C0603]
C26  22uF  [C0603]
C27  22uF  [C0603]
C67  1uF  [C0402]
CN1  DC10B  [CON_DC-POWER-SOCKET_CLIFF_FC68149_DC10B]
CN5  Header 4 pins  Fitted: NO  [CON_SAMTEC_TSW-104-07-G-S]
D1  SMAJ5.0A  [DIO_SMA_DO214-AC_1A_2K]
F1  PTC FUSE 2.6A  [PTC_BEL-FUSE_1812_0ZCG0260FF2C]
L1  Manuf_Part_1: DFE252012P-1R0M=P2  [IND_2520_TOKO_DFE252012P]  (hidden comment: 1uH)
L2  Manuf_Part_1: DFE252012P-1R0M=P2  [IND_2520_TOKO_DFE252012P]  (hidden comment: 1uH)
L3  Manuf_Part_1: DFE252012P-1R0M=P2  [IND_2520_TOKO_DFE252012P]  (hidden comment: 1uH)
L4  Manuf_Part_1: DFE252012P-1R0M=P2  [IND_2520_TOKO_DFE252012P]  (hidden comment: 1uH)
L5  Manuf_Part_1: DFE252012P-1R0M=P2  [IND_2520_TOKO_DFE252012P]  (hidden comment: 1uH)
LD1  value GREEN  [LED_0603_GREEN]  (hidden comment: LED_green)
LNK1  link_200  (value not drawn)  (no BOM)
LNK2  link_200  (value not drawn)  (no BOM)
R1  39R 1%  Fitted: NO  [R0402]
R2  330R  [R0402]
R7  0R_0603_ULO  [R0603]
R15  0R  [R0402]
R50  0R_0603_ULO  [R0603]
R59  0R_0603_ULO  [R0603]
R60  0R_0603_ULO  [R0603]
R61  0R_0603_ULO  [R0603]
R62  0R_0603_ULO  [R0603]
R63  0R_0603_ULO  [R0603]
R64  0R_0603_ULO  [R0603]
R68  0R_0603_ULO  [R0603]
R72  0R_0603_ULO  [R0603]
R75  0R_0603_ULO  [R0603]
R76  0R_0603_ULO  [R0603]
R77  0R_0603_ULO  [R0603]
R78  0R_0603_ULO  [R0603]
R79  0R_0603_ULO  [R0603]
R80  0R_0603_ULO  [R0603]
R81  0R_0603_ULO  [R0603]
R82  0R_0603_ULO  [R0603]
R83  0R_0603_ULO  [R0603]
R84  0R_0603_ULO  [R0603]
R85  0R_0603_ULO  [R0603]
R86  0R_0603_ULO  [R0603]
R87  0R_0603_ULO  [R0603]
TP2  TP  [TP_SMD_1MM]  (value not drawn)  (no BOM)
U1  STEF05LPUR  Fitted: NO  [ICC_DFN10-EPAD_3X3_P050]
U3  STPMIC1APQR  [ICC_WFQFN44-EPAD_5X6_P040]

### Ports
I2C4_SCL (in), I2C4_SDA (bidir), NRST (bidir), PA0_WKUP (out), PMIC_WAKEUP (in), POWER_ON (in)

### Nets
1V8: R76.2
2V8: R75.2
3V3: R61.1 R62.1 R87.2 U3.27(VOUT_4)
BST_OUT: C12.2 U3.34(BST_OUT) U3.37(SW_IN)
GND: B4.1 B4.2 C1.2 C2.1 C3.1 C4.1 C5.1 C6.1 C7.1 C8.1 C9.1 C10.1 C11.1 C12.1 C13.1 C14.1 C15.1 C16.1 C17.1 C19.1 C20.2 C21.1 C22.1 C23.1 C24.1 C25.1 C26.1 C27.1 C67.1 CN1.2 CN1.3 CN5.3 D1.1(A) LD1.2 U1.10(GND) U3.6(PGND1) U3.10(PGND2) U3.15(GNDLDO) U3.26(PGND4) U3.30(PGND3) U3.32(PGND5) U3.41(AGND) U3.ep(EP_GND)
VBUS_OTG: R85.2
VBUS_SW: R84.2
VDD: R15.2 R64.1 R82.2 U3.31(VOUT_3)
VDD_CORE: LNK1.2 R81.2
VDD_DDR: LNK2.2 R79.1 R80.2
VDD_SD: R77.2
VDD_USB: R83.2
VDDA: R86.2
VIN: C1.1 C4.2 R2.2 R7.2 R50.1 R59.1 R60.1 R63.1 R68.1 R72.1 U1.1(VOUT1) U1.2(VOUT2) U1.3(VOUT3) U1.4(VOUT4) U1.5(VOUT5)
VIN_JACK: C2.2 CN1.1 F1.1
VREF_DDR: C19.2 U3.16(VREF)
VTT_DDR: R78.2
I2C4_SCL: CN5.2 U3.4(SCL) ; port I2C4_SCL
I2C4_SDA: CN5.4 U3.3(SDA) ; port I2C4_SDA
NRST: U3.1(RST_N) ; port NRST
PA0_WKUP: U3.43(INT_N) ; port PA0_WKUP
PMIC_WAKEUP: U3.2(WAKEUP) ; port PMIC_WAKEUP
POWER_ON: TP2.1 U3.44(PWRCTRL) ; port POWER_ON
NetB4_3: B4.3 B4.4 C5.2 U3.17(PONKEY_N)
NetC3_2: C3.2 D1.2(K) F1.2 R7.1 U1.EP(VCC_EP)
NetC6_2: C6.2 L1.2 R82.1
NetC7_2: C7.2 L2.2 R87.1
NetC8_2: C8.2 L3.1 R59.2
NetC9_2: C9.2 R50.2 U3.28(BUCK3_IN)
NetC10_2: C10.2 R60.2 U3.24(BUCK4_IN)
NetC11_2: C11.2 R86.1 U3.23(LDO1_OUT)
NetC13_2: C13.2 R76.1 U3.21(LDO6_OUT)
NetC14_2: C14.2 R63.2 U3.36(VIN)
NetC15_2: C15.2 R77.1 U3.20(LDO5_OUT)
NetC16_2: C16.2 R62.2 U3.19(LDO25_IN)
NetC17_2: C17.2 R75.1 U3.18(LDO2_OUT)
NetC20_1: C20.1 U3.40(INT_LDO)
NetC21_2: C21.2 R83.1 U3.39(LDO4_OUT)
NetC22_2: C22.2 R78.1 U3.14(LDO3_OUT)
NetC23_2: C23.2 R79.2 U3.13(LDO3_IN)
NetC24_2: C24.2 R68.2 U3.12(BUCK2_IN)
NetC25_2: C25.2 R72.2 U3.8(BUCK1_IN)
NetC26_2: C26.2 L4.2 R80.1
NetC27_2: C27.2 L5.2 R81.1
NetC67_2: C67.2 R61.2 U3.22(LDO16_IN)
NetCN5_1: CN5.1 R15.1
NetL1_1: L1.1 U3.29(VLX_3)
NetL2_1: L2.1 U3.25(VLX_4)
NetL3_2: L3.2 U3.33(VLX_BST)
NetL4_1: L4.1 U3.11(VLX_2)
NetL5_1: L5.1 U3.7(VLX_1)
NetLD1_1: LD1.1 R2.1
NetLNK1_1: LNK1.1 U3.5(VOUT_1)
NetLNK2_1: LNK2.1 U3.9(VOUT_2)
NetR1_1: R1.1 U1.7(I_LIM+)
NetR1_2: R1.2 U1.6(I_LIM-)
NetR64_2: R64.2 U3.42(VIO)
NetR84_1: R84.1 U3.38(SW_OUT)
NetR85_1: R85.1 U3.35(VBUS_OTG)

Not connected (* = marked no-connect by the designer): U1 8(EN_FAULT)* 9(dv/dt)*

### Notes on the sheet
- put decap close to USB connector
- (near R64) PZ5
- (near R64) PZ4
- PA0
- NRST
- (near R64) PWR_ON
- PC13

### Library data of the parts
B4 = SW-PUSH-TS-02H-Blue: TS-02H SMD Light Touch Switch blue; Manuf_1: Jiubaba; Manuf_Part_1: C-TS-02H-2.5-K-V-T/R BLUE; Fitted: YES; Ordered_By: subcon
C1 = Cap_220uF_POL_10%_TAJA: Polarized Capacitor,220uF,10V,10%,AVX; Manuf_Part_1: TAJC227K010R; Fitted: YES; Ordered_By: Subcon
C2 = Cap_100nF_X7R_10%_0402: as C41 on sheet eMMC
C3 C4 = Cap_1uF_X5R_10%_0603: Capacitor,1uF,16V,X5R,10%,0603,YAGEO; Manuf_Part_1: CC0603KRX5R7BB105; Fitted: YES; Ordered_By: Subcon
C5 = Cap_10nF_X7R_10%_0402: Capacitor,10nF,16V,X7R,10%,0402,YAGEO; Manuf_Part_1: CC0402KRX7R7BB103; Fitted: YES; Ordered_By: Subcon
C6 C7 C12 C26 C27 = Cap_22uF_X5R_20%_0603_MURATA: as C133 on sheet DDR3_2x16bits
C8-C10 C22-C25 = Cap_10uF_X5R_10%_0603_MURATA: Capacitor MLCC 10µF 10% 10V 2,5µF@5,5V Z=5mohm@2MHz X5R 0603; Manuf_Part_1: GRM188R61A106KE69D; Manuf_1: MURATA; Fitted: YES; Ordered_By: Subcon
C11 C13-C15 C17 C20 C21 = Cap_4.7uF_X5R_20%_6V3_0402: Capacitor MLCC 4,7µF 20% 6,3V 1,9uF@3,3V X5R 0402; Manuf_Part_1: GRM155R60J475ME47; Manuf_1: MURATA; Fitted: YES; Ordered_By: Subcon
C16 C19 C67 = Cap_1uF_X5R_10%_6V3_0402: Capacitor MLCC 1µF 10% 6,3V 0,4uF@3,3V X5R 0402 MURATA; Manuf_Part_1: GRM155R61E105KA12; Fitted: YES; Ordered_By: Subcon
CN1 = CONN_Power_DC10B: DC Power Jack 2.5mm 5A Right Angle through hole; Manuf_Part_1: DC-10B; Manuf_1: CLIFF; Ordered_By: Subcon; Fitted: YES
CN5 = Header 4: Header, 4-Pin; Manuf_1: Samtec; Manuf_Part_1: TSW-104-07-x-S; Ordered_By: Subcon
D1 = SMAJ5.0A-TR: Transil unidirectional diode Vrm=5.0V, Vbr=6.4V(10mA), Vcl=13.4V(174A), SMA; Manuf_1: STM; Ordered_By: Subcon; ECCN_US/EU: EAR99/NEC; Fitted: YES
F1 = 0ZCG0260FF2C: SMD, PTC resettable fuse, IH:2.6A, IT:5A, Vdc_max:8V, Rmax:47mohm, BELFUSE; Fitted: YES; Ordered_By: Subcon
L1-L5 = IND_1uH_42mohm_3.2A: SMD power inductor. 1µH, 3,2A, 42mohm, 2,5x2,0x1,2mm; Manuf_1: Murata; Ordered_By: Subcon; Fitted: YES
LD1 = MCD-02900: LED, Green, 2V, 25mA, 0603, SMD; Part_Type: Display; Part_Preference: Recommended; Manufacturer: EVERLIGHT; Manufacturer_Part_Number: 19-213SYGC/S530-E2/5T; Full_Alternate_Internal_Part_Number: MCD-00320; Partial_Alternate_Internal_Part_Number: MCD-00050; Component_Country_Of_Origin: China; ShowFields: YES; ID: 5016
LNK1 LNK2 = link_200: link 0.2mm
R1 = Res_39_1%_0402: Resistor,39R,0402,1%,YAGEO; Manuf_Part_1: RC0402FR-0739RL; Ordered_By: Subcon
R2 = Res_330_1%_0402: Resistor,330R,0402,1%,YAGEO; Manuf_Part_1: RC0402FR-07330RL; Fitted: YES; Ordered_By: Subcon
R7 R50 R59-R64 R68 R72 R75-R87 = Res_0_ULO_0603: Resistor,0R,0603,ULO,ROHM; Manuf_Part_1: PMR03EZPJ000; Fitted: YES; Ordered_By: subcon
R15 = Res_0_5%_0402: Resistor,0R,0402,5%,YAGEO; Manuf_Part_1: RC0402JR-070RL; Order_Code: 2363467; Fitted: YES; Ordered_By: Subcon
TP2 = TP 1mm: Test Point; Fitted: YES
U1 = STEF05LPUR: Electronic fuse for 5V line, 3.6A max, DFN10(3x3mm); Manuf_1: STM; Ordered_By: Subcon
U3 = STPMIC1A: PMIC WFQFN 5.0x6.0x0.8 44L 0.4 pitch; Provided: ST; Ordered_By: Subcon; ECCN_US/EU: EAR99/NEC; Fitted: YES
